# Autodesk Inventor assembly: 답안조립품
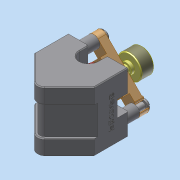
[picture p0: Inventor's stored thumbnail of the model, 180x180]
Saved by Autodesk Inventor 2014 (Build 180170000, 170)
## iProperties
Created: 2025-02
Part Number: 답안조립품
Document SubType Name: Assembly
Designer: dg
Author: dg
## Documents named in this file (9)
- C:\Users\dg\Desktop\750203V1006\답안조립품.iam
- C:\Users\dg\Desktop\750203V1006\본체.ipt
- C:\Users\dg\Desktop\750203V1006\가져온 구성요소\노브\노브.ipt
- C:\Users\dg\Desktop\750203V1006\가져온 구성요소\서포터\서포터.ipt
- C:\Users\dg\Desktop\750203V1006\가져온 구성요소\스트리퍼 볼트 M6x10\스트리퍼 볼트 M6x10.ipt
- C:\Users\dg\Desktop\750203V1006\가져온 구성요소\조\조.ipt
- C:\Users\dg\Desktop\750203V1006\가져온 구성요소\드릴부시\드릴부시.ipt
- C:\Users\dg\Desktop\750203V1006\가져온 구성요소\가공품\가공품.ipt
- C:\Users\dg\Desktop\750203V1006\가져온 구성요소\고정핀\고정핀.ipt
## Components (2 placed, 2 different names)
1. 가공품:1
2. 고정핀:1
